Omron CX-Programmer project NewProject (CX-Programmer 9.11)

# PLC NewPLC1: CQM1H CPU21

## Program NewProgram1 (no task)
Local symbols
Destination_Words DM300 WORD
IO_Command_Area DM100 WORD
Read_Values 16.02 BOOL
Ready 16.01 BOOL
Source_Words DM200 WORD

### Section Section1

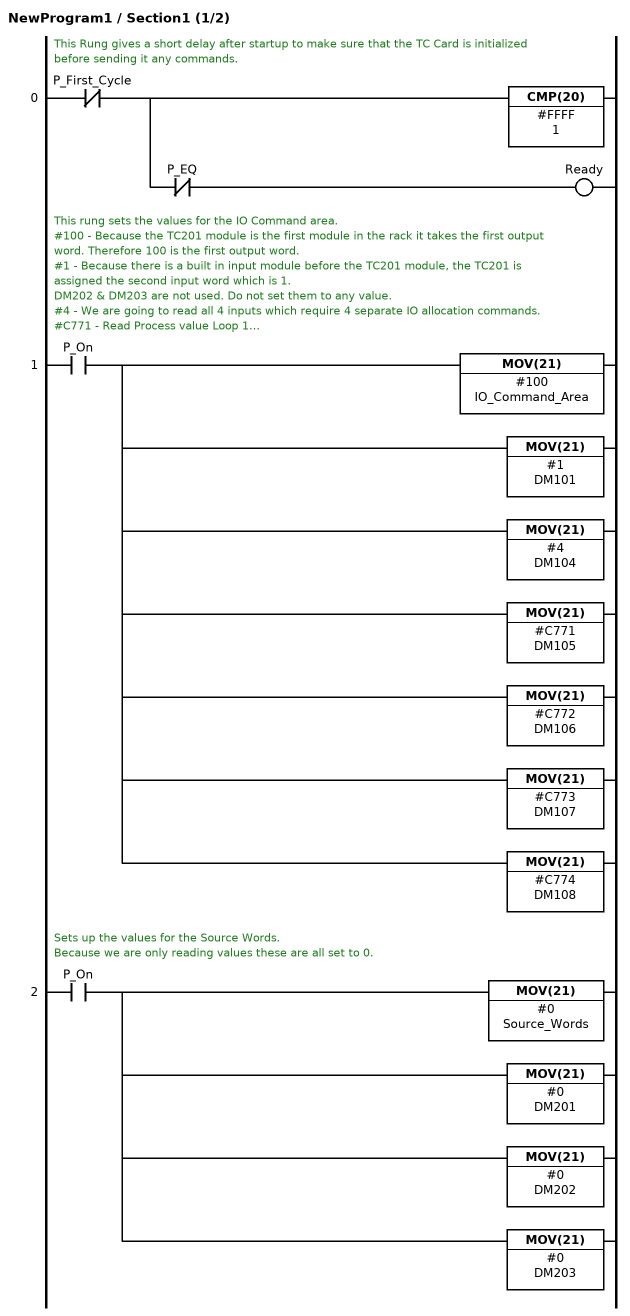
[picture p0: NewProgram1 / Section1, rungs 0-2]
; rung 0: This Rung gives a short delay after startup to make sure that the TC Card is initialized before sending it any commands.
LDNOT P_First_Cycle
CMP(20) #FFFF 1
ANDNOT P_EQ
OUT Ready
; rung 1: This rung sets the values for the IO Command area. / #100 - Because the TC201 module is the first module in the rack it takes the first output word. Therefore 100 is the first output word. / #1 - Because there is a built in input module before the TC201 module, the TC201 is assigned the second input word which is 1. / DM202 & DM203 are not used. Do not set them to any value. / #4 - We are going to read all 4 inputs which require 4 separate IO allocation commands. / #C771 - Read Process value Loop 1. / #C772 - Read Process value Loop 2. / #C773 - Read Process value Loop 3. / #C774 - Read Process value Loop 4.
LD P_On
MOV(21) #100 IO_Command_Area
MOV(21) #1 DM101
MOV(21) #4 DM104
MOV(21) #C771 DM105
MOV(21) #C772 DM106
MOV(21) #C773 DM107
MOV(21) #C774 DM108
; rung 2: Sets up the values for the Source Words. / Because we are only reading values these are all set to 0.
LD P_On
MOV(21) #0 Source_Words
MOV(21) #0 DM201
MOV(21) #0 DM202
MOV(21) #0 DM203

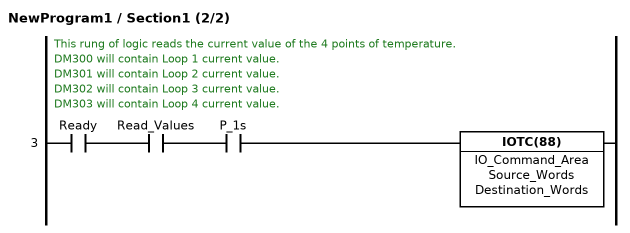
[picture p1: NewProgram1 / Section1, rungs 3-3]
; rung 3: This rung of logic reads the current value of the 4 points of temperature. / DM300 will contain Loop 1 current value. / DM301 will contain Loop 2 current value. / DM302 will contain Loop 3 current value. / DM303 will contain Loop 4 current value.
LD Ready
AND Read_Values
AND P_1s
IOTC(88) IO_Command_Area Source_Words Destination_Words

### Section END
; rung 0
END(01)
